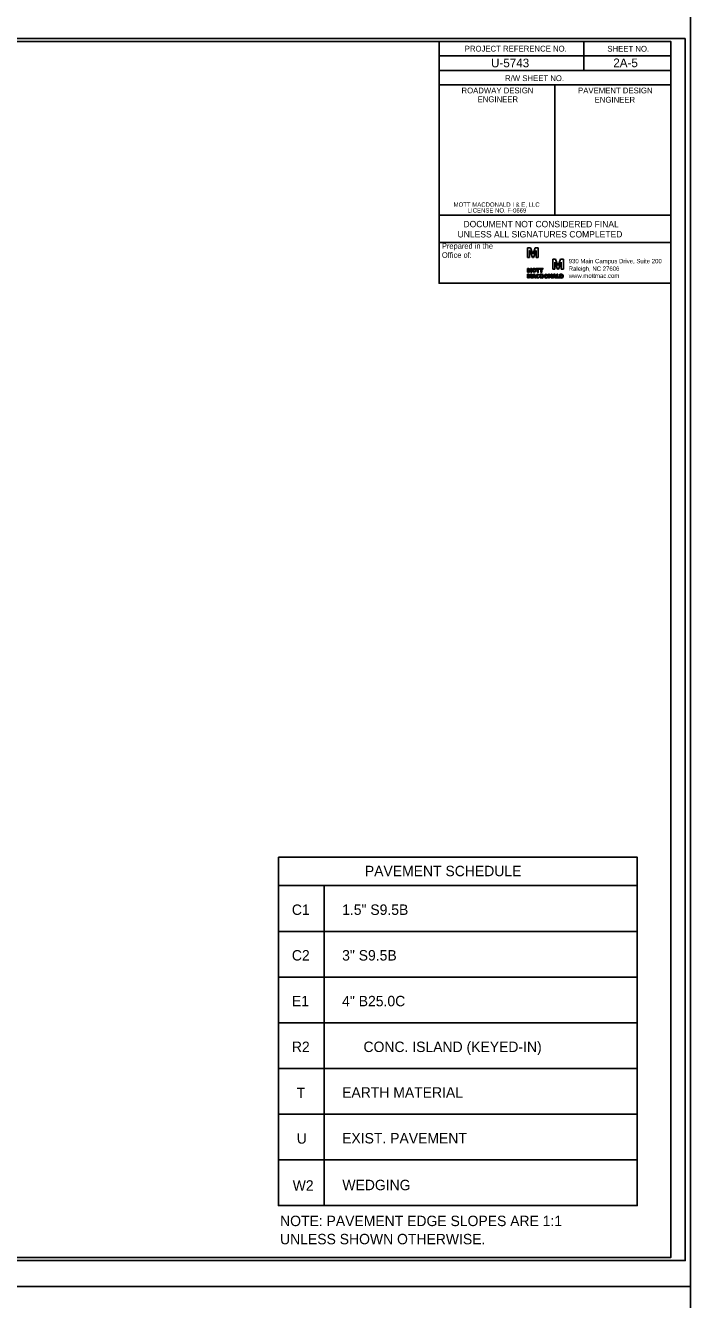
# Model space of a CAD drawing. Extents: x 1901670 to 1902225, y 193498 to 194278.
# Drawn here: x 1902076.8 to 1902134.2, y 193716.9 to 193826.9 of the extents above; entities that cross this region are included whole.
import ezdxf

# ---------------------------------------------------------------- set-up
doc = ezdxf.new("R2010")
doc.units = 0
for name, color, linetype in [('Old_Level_2', 7, 'Continuous'), ('Old_Level_42', 7, 'Continuous'), ('Old_Level_45', 7, 'Continuous'), ('Prop Dimension Text', 7, 'Continuous'), ('Prop Pavement Schedule Description CELL', 7, 'Continuous'), ('Sheet Border Standard 30in CELL', 7, 'Continuous'), ('Sheet Cutting Line CELL', 7, 'Continuous'), ('Sheet Data Field CELL', 7, 'Continuous'), ('Sheet Plot Border Inside CELL', 7, 'Continuous'), ('Sheet Plot Border Outside CELL', 7, 'Continuous'), ('Sheet Sticker Exception Certification CELL', 7, 'Continuous')]:
    doc.layers.add(name, color=color, linetype=linetype)

msp = doc.modelspace()

# ---------------------------------------------------------------- linework, layer by layer
at = {"layer": 'Old_Level_2'}
for p, q in [((1902120.44, 193807.7), (1902120.18, 193807.7)), ((1902120.18, 193807.7), (1902120.18, 193806.85)), ((1902120.18, 193806.85), (1902120.36, 193806.85)), ((1902120.36, 193806.85), (1902120.36, 193807.46)), ((1902120.36, 193807.46), (1902120.37, 193807.46)), ((1902120.37, 193807.46), (1902120.61, 193806.85)), ((1902120.64, 193807.17), (1902120.44, 193807.7)), ((1902120.61, 193806.85), (1902120.68, 193806.85)), ((1902120.65, 193807.17), (1902120.64, 193807.17)), ((1902120.64, 193807.17), (1902120.64, 193807.17)), ((1902120.85, 193807.7), (1902120.65, 193807.17)), ((1902120.65, 193807.17), (1902120.65, 193807.17)), ((1902120.68, 193806.85), (1902120.92, 193807.46)), ((1902121.1, 193807.7), (1902120.85, 193807.7)), ((1902120.92, 193807.46), (1902120.93, 193807.46)), ((1902120.93, 193807.46), (1902120.93, 193806.85)), ((1902120.93, 193806.85), (1902121.1, 193806.85)), ((1902121.1, 193806.85), (1902121.1, 193807.7)), ((1902120.28, 193805.92), (1902120.18, 193805.92)), ((1902120.18, 193805.92), (1902120.18, 193805.59)), ((1902120.25, 193805.59), (1902120.25, 193805.83)), ((1902120.25, 193805.83), (1902120.25, 193805.83)), ((1902120.25, 193805.83), (1902120.35, 193805.59)), ((1902120.25, 193805.83), (1902120.25, 193805.83)), ((1902120.36, 193805.72), (1902120.28, 193805.92)), ((1902120.44, 193805.92), (1902120.36, 193805.72)), ((1902120.38, 193805.59), (1902120.47, 193805.83)), ((1902120.54, 193805.92), (1902120.44, 193805.92)), ((1902120.47, 193805.83), (1902120.47, 193805.83)), ((1902120.47, 193805.83), (1902120.47, 193805.59)), ((1902120.47, 193805.83), (1902120.47, 193805.83)), ((1902120.47, 193805.83), (1902120.47, 193805.83)), ((1902120.54, 193805.59), (1902120.54, 193805.92)), ((1902120.54, 193805.59), (1902120.54, 193805.92)), ((1902122.6, 193806.71), (1902122.35, 193806.71)), ((1902122.35, 193806.71), (1902122.35, 193805.86)), ((1902122.35, 193805.86), (1902122.53, 193805.86)), ((1902122.53, 193805.86), (1902122.53, 193806.47)), ((1902122.53, 193806.47), (1902122.53, 193806.47)), ((1902122.53, 193806.47), (1902122.77, 193805.86)), ((1902122.8, 193806.18), (1902122.6, 193806.71)), ((1902122.77, 193805.86), (1902122.85, 193805.86)), ((1902122.81, 193806.18), (1902122.8, 193806.18)), ((1902122.8, 193806.18), (1902122.8, 193806.18)), ((1902123.01, 193806.71), (1902122.81, 193806.18)), ((1902122.81, 193806.18), (1902122.81, 193806.18)), ((1902122.85, 193805.86), (1902123.08, 193806.47)), ((1902123.27, 193806.71), (1902123.01, 193806.71)), ((1902123.08, 193806.47), (1902123.09, 193806.47)), ((1902123.09, 193806.47), (1902123.09, 193805.86)), ((1902123.09, 193805.86), (1902123.27, 193805.86)), ((1902123.27, 193805.86), (1902123.27, 193806.71)), ((1902120.18, 193805.59), (1902120.25, 193805.59)), ((1902120.28, 193805.41), (1902120.18, 193805.41)), ((1902120.18, 193805.41), (1902120.18, 193805.09)), ((1902120.18, 193805.09), (1902120.25, 193805.09)), ((1902120.25, 193805.09), (1902120.25, 193805.32)), ((1902120.25, 193805.32), (1902120.25, 193805.32)), ((1902120.25, 193805.32), (1902120.35, 193805.09)), ((1902120.36, 193805.21), (1902120.28, 193805.41)), ((1902120.35, 193805.59), (1902120.38, 193805.59)), ((1902120.35, 193805.09), (1902120.38, 193805.09)), ((1902120.44, 193805.41), (1902120.36, 193805.21)), ((1902120.38, 193805.09), (1902120.47, 193805.32)), ((1902120.54, 193805.41), (1902120.44, 193805.41)), ((1902120.47, 193805.59), (1902120.54, 193805.59)), ((1902120.47, 193805.32), (1902120.47, 193805.32)), ((1902120.47, 193805.32), (1902120.47, 193805.09)), ((1902120.47, 193805.09), (1902120.54, 193805.09)), ((1902120.54, 193805.09), (1902120.54, 193805.41)), ((1902121.22, 193805.16), (1902121.16, 193805.18)), ((1902121.22, 193805.16), (1902121.16, 193805.18)), ((1902121.17, 193805.31), (1902121.23, 193805.33)), ((1902121.17, 193805.31), (1902121.23, 193805.33)), ((1902121.42, 193805.41), (1902121.27, 193805.41)), ((1902121.27, 193805.41), (1902121.27, 193805.25)), ((1902121.27, 193805.25), (1902121.27, 193805.09)), ((1902121.27, 193805.09), (1902121.42, 193805.09)), ((1902121.34, 193805.15), (1902121.34, 193805.35)), ((1902121.34, 193805.35), (1902121.42, 193805.35)), ((1902121.42, 193805.15), (1902121.34, 193805.15)), ((1902122.96, 193805.41), (1902122.96, 193805.41)), ((1902123.1, 193805.41), (1902122.96, 193805.41)), ((1902122.96, 193805.41), (1902122.96, 193805.25)), ((1902122.96, 193805.25), (1902122.96, 193805.09)), ((1902122.96, 193805.09), (1902123.1, 193805.09)), ((1902123.02, 193805.15), (1902123.02, 193805.35)), ((1902123.02, 193805.35), (1902123.1, 193805.35)), ((1902123.1, 193805.15), (1902123.02, 193805.15)), ((1902123.1, 193805.35), (1902123.1, 193805.35))]:
    msp.add_line(p, q, dxfattribs=at)
for points in [[(1902120.95, 193805.86), (1902121.04, 193805.86), (1902121.04, 193805.59), (1902121.11, 193805.59), (1902121.11, 193805.86), (1902121.2, 193805.86), (1902121.2, 193805.92), (1902120.95, 193805.92), (1902120.95, 193805.86)], [(1902121.24, 193805.86), (1902121.34, 193805.86), (1902121.34, 193805.59), (1902121.41, 193805.59), (1902121.41, 193805.86), (1902121.5, 193805.86), (1902121.5, 193805.92), (1902121.24, 193805.92), (1902121.24, 193805.86)], [(1902120.58, 193805.09), (1902120.65, 193805.09), (1902120.68, 193805.14), (1902120.82, 193805.14), (1902120.84, 193805.09), (1902120.91, 193805.09), (1902120.79, 193805.41), (1902120.7, 193805.41), (1902120.58, 193805.09)], [(1902120.69, 193805.2), (1902120.75, 193805.34), (1902120.8, 193805.2), (1902120.69, 193805.2)], [(1902122.07, 193805.3), (1902122.07, 193805.3), (1902122.23, 193805.09), (1902122.29, 193805.09), (1902122.29, 193805.41), (1902122.23, 193805.41), (1902122.23, 193805.21), (1902122.07, 193805.41), (1902122, 193805.41), (1902122, 193805.09), (1902122.07, 193805.09), (1902122.07, 193805.3)], [(1902122.33, 193805.09), (1902122.41, 193805.09), (1902122.43, 193805.14), (1902122.57, 193805.14), (1902122.59, 193805.09), (1902122.67, 193805.09), (1902122.54, 193805.41), (1902122.46, 193805.41), (1902122.33, 193805.09)], [(1902122.45, 193805.2), (1902122.5, 193805.34), (1902122.56, 193805.2), (1902122.45, 193805.2)], [(1902122.92, 193805.09), (1902122.92, 193805.15), (1902122.78, 193805.15), (1902122.78, 193805.41), (1902122.71, 193805.41), (1902122.71, 193805.09), (1902122.92, 193805.09)], [(1902122.92, 193805.09), (1902122.92, 193805.15), (1902122.78, 193805.15), (1902122.78, 193805.41), (1902122.71, 193805.41), (1902122.71, 193805.09), (1902122.92, 193805.09), (1902122.92, 193805.15)]]:
    msp.add_lwpolyline(points, dxfattribs=at)
msp.add_arc((1902123.1, 193805.25), 0.162, 270, 90, dxfattribs=at)
for centre, major_axis, ratio in [((1902120.76, 193805.76), (0, 0.162), 0.993118), ((1902120.76, 193805.76), (0, 0.106), 0.916103), ((1902121.79, 193805.25), (0, 0.162), 0.993118), ((1902121.79, 193805.25), (0, 0.106), 0.916103)]:
    msp.add_ellipse(centre, major_axis=major_axis, ratio=ratio, dxfattribs=at)
for centre, major_axis, ratio, start_param, end_param in [((1902121.09, 193805.25), (0, 0.162), 0.993118, 5.246647, 10.366427), ((1902121.09, 193805.25), (0, 0.162), 0.993118, 5.246647, 10.366427), ((1902121.09, 193805.25), (0, 0.106), 0.916103, 5.276876, 9.424778), ((1902121.09, 193805.25), (0, 0.106), 0.916103, 5.276876, 10.296021), ((1902121.09, 193805.25), (0, 0.106), 0.916103, 3.141593, 4.012835), ((1902121.42, 193805.25), (0, -0.162), 0.930276, 0, 3.141593), ((1902121.42, 193805.25), (0, -0.101), 0.900832, 0, 3.141593), ((1902123.1, 193805.25), (0, -0.101), 0.900832, 0, 3.141593)]:
    msp.add_ellipse(centre, major_axis=major_axis, ratio=ratio, start_param=start_param, end_param=end_param, dxfattribs=at)
at = {"layer": 'Old_Level_42'}
msp.add_lwpolyline([(1902132.54, 193804.63), (1902112.54, 193804.63), (1902112.54, 193808.16)], dxfattribs=at)
at = {"layer": 'Prop Pavement Schedule Description CELL'}
msp.add_lwpolyline([(1902098.68, 193755.08), (1902129.65, 193755.08), (1902129.65, 193752.63), (1902098.68, 193752.63)], close=True, dxfattribs=at)
for points in [[(1902102.63, 193748.68), (1902098.68, 193748.68), (1902098.68, 193752.63), (1902129.65, 193752.63), (1902129.65, 193748.68), (1902102.63, 193748.68), (1902102.63, 193752.63)], [(1902102.63, 193744.73), (1902098.68, 193744.73), (1902098.68, 193748.68), (1902129.65, 193748.68), (1902129.65, 193744.73), (1902102.63, 193744.73), (1902102.63, 193748.68)], [(1902102.63, 193740.79), (1902098.68, 193740.79), (1902098.68, 193744.73), (1902129.65, 193744.73), (1902129.65, 193740.79), (1902102.63, 193740.79), (1902102.63, 193744.73)], [(1902102.63, 193736.84), (1902098.68, 193736.84), (1902098.68, 193740.79), (1902129.65, 193740.79), (1902129.65, 193736.84), (1902102.63, 193736.84), (1902102.63, 193740.79)], [(1902102.63, 193732.89), (1902098.68, 193732.89), (1902098.68, 193736.84), (1902129.65, 193736.84), (1902129.65, 193732.89), (1902102.63, 193732.89), (1902102.63, 193736.84)], [(1902102.63, 193728.95), (1902098.68, 193728.95), (1902098.68, 193732.89), (1902129.65, 193732.89), (1902129.65, 193728.95), (1902102.63, 193728.95), (1902102.63, 193732.89)], [(1902102.63, 193725), (1902098.68, 193725), (1902098.68, 193728.95), (1902129.65, 193728.95), (1902129.65, 193725), (1902102.63, 193725), (1902102.63, 193728.95)]]:
    msp.add_lwpolyline(points, dxfattribs=at)
at = {"layer": 'Sheet Border Standard 30in CELL'}
for p, q in [((1902125.04, 193825.51), (1902125.04, 193823.01)), ((1902112.54, 193824.26), (1902132.54, 193824.26)), ((1902112.54, 193823.01), (1902132.54, 193823.01)), ((1902112.54, 193823.01), (1902112.54, 193821.76)), ((1902112.54, 193823.01), (1902132.54, 193823.01)), ((1902122.54, 193821.76), (1902122.54, 193810.51))]:
    msp.add_line(p, q, dxfattribs=at)
for points in [[(1902132.54, 193825.51), (1901982.54, 193825.51), (1901982.54, 193720.51), (1902132.54, 193720.51)], [(1902112.54, 193825.51), (1902132.54, 193825.51), (1902132.54, 193823.01), (1902112.54, 193823.01)], [(1902112.54, 193821.76), (1902122.54, 193821.76), (1902122.54, 193810.51), (1902112.54, 193810.51)], [(1902122.54, 193821.76), (1902132.54, 193821.76), (1902132.54, 193810.51), (1902122.54, 193810.51)]]:
    msp.add_lwpolyline(points, close=True, dxfattribs=at)
at = {"layer": 'Sheet Cutting Line CELL'}
for p, q in [((1901965.84, 193718.01), (1902134.24, 193718.01)), ((1902134.24, 193718.01), (1901965.84, 193718.01))]:
    msp.add_line(p, q, dxfattribs=at)
at = {"layer": 'Sheet Plot Border Inside CELL'}
msp.add_lwpolyline([(1902133.79, 193825.77), (1901967.14, 193825.77), (1901967.14, 193720.26), (1902133.79, 193720.26)], close=True, dxfattribs=at)
at = {"layer": 'Sheet Plot Border Outside CELL'}
for points in [[(1902134.24, 193828.01), (1901965.84, 193828.01), (1901965.84, 193718.01), (1902134.24, 193718.01)], [(1902134.24, 193718.01), (1901965.84, 193718.01), (1901965.84, 193608.01), (1902134.24, 193608.01)]]:
    msp.add_lwpolyline(points, close=True, dxfattribs=at)
at = {"layer": 'Sheet Sticker Exception Certification CELL'}
for p, q in [((1902112.54, 193808.16), (1902112.54, 193810.51)), ((1902112.54, 193810.51), (1902132.54, 193810.51)), ((1902132.54, 193810.51), (1902132.54, 193808.16)), ((1902132.54, 193808.16), (1902112.54, 193808.16))]:
    msp.add_line(p, q, dxfattribs=at)

# ---------------------------------------------------------------- texts
at = {"layer": 'Old_Level_2'}
for s, height, p in [('Prepared in the ', 0.4819, (1902112.79, 193807.61)), ('Office of:', 0.482, (1902112.79, 193806.83))]:
    msp.add_text(s, height=height, dxfattribs=at).set_placement(p)
for s, p in [('930 Main Campus Drive, Suite 200', (1902123.73, 193806.36)), ('Raleigh, NC 27606', (1902123.73, 193805.71)), ('www.mottmac.com ', (1902123.73, 193805.1))]:
    msp.add_text(s, height=0.375, rotation=360, dxfattribs=at).set_placement(p)
at = {"layer": 'Old_Level_45'}
for s, p in [('MOTT MACDONALD I & E, LLC', (1902113.8, 193811.24)), (' LICENSE NO. F-0669', (1902114.87, 193810.74))]:
    msp.add_text(s, height=0.375, rotation=360, dxfattribs=at).set_placement(p)
at = {"layer": 'Prop Dimension Text'}
msp.add_text('PAVEMENT SCHEDULE', height=0.9, dxfattribs=at).set_placement((1902106.14, 193753.44))
at = {"layer": 'Prop Pavement Schedule Description CELL'}
for s, p in [('C1', (1902099.84, 193750.1)), ('    1.5" S9.5B', (1902102.84, 193750.1)), ('C2', (1902099.84, 193746.16)), ('    3" S9.5B', (1902102.84, 193746.16)), ('E1', (1902099.84, 193742.21)), ('    4" B25.0C', (1902102.84, 193742.21)), ('R2', (1902099.84, 193738.26)), ('CONC. ISLAND (KEYED-IN)', (1902106.02, 193738.26)), ('T', (1902100.25, 193734.28)), ('    EARTH MATERIAL', (1902102.84, 193734.32)), ('U', (1902100.26, 193730.35)), ('    EXIST. PAVEMENT', (1902102.84, 193730.37)), ('W2', (1902099.91, 193726.29)), ('    WEDGING', (1902102.86, 193726.33)), ('NOTE: PAVEMENT EDGE SLOPES ARE 1:1', (1902098.82, 193723.23)), ('UNLESS SHOWN OTHERWISE.', (1902098.82, 193721.66))]:
    msp.add_text(s, height=0.9, dxfattribs=at).set_placement(p)
at = {"layer": 'Sheet Border Standard 30in CELL'}
for s, p in [('PROJECT REFERENCE NO.', (1902114.76, 193824.64)), ('SHEET NO.', (1902127.07, 193824.63)), ('R/W SHEET NO.', (1902118.24, 193822.09)), ('ROADWAY DESIGN', (1902114.48, 193821.03)), ('PAVEMENT DESIGN', (1902124.54, 193821.03)), ('ENGINEER', (1902115.87, 193820.27)), ('ENGINEER', (1902125.97, 193820.23))]:
    msp.add_text(s, height=0.5, dxfattribs=at).set_placement(p)
at = {"layer": 'Sheet Data Field CELL'}
for s, p in [('U-5743', (1902117.03, 193823.28)), ('2A-5', (1902127.58, 193823.29))]:
    msp.add_text(s, height=0.75, dxfattribs=at).set_placement(p)
at = {"layer": 'Sheet Sticker Exception Certification CELL'}
for s, p in [('UNLESS ALL SIGNATURES COMPLETED', (1902114.14, 193808.59)), ('DOCUMENT NOT CONSIDERED FINAL', (1902114.65, 193809.47))]:
    msp.add_text(s, height=0.55, dxfattribs=at).set_placement(p)

doc.saveas('drawing.dxf')
